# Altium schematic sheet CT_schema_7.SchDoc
size 430 x 429 mm
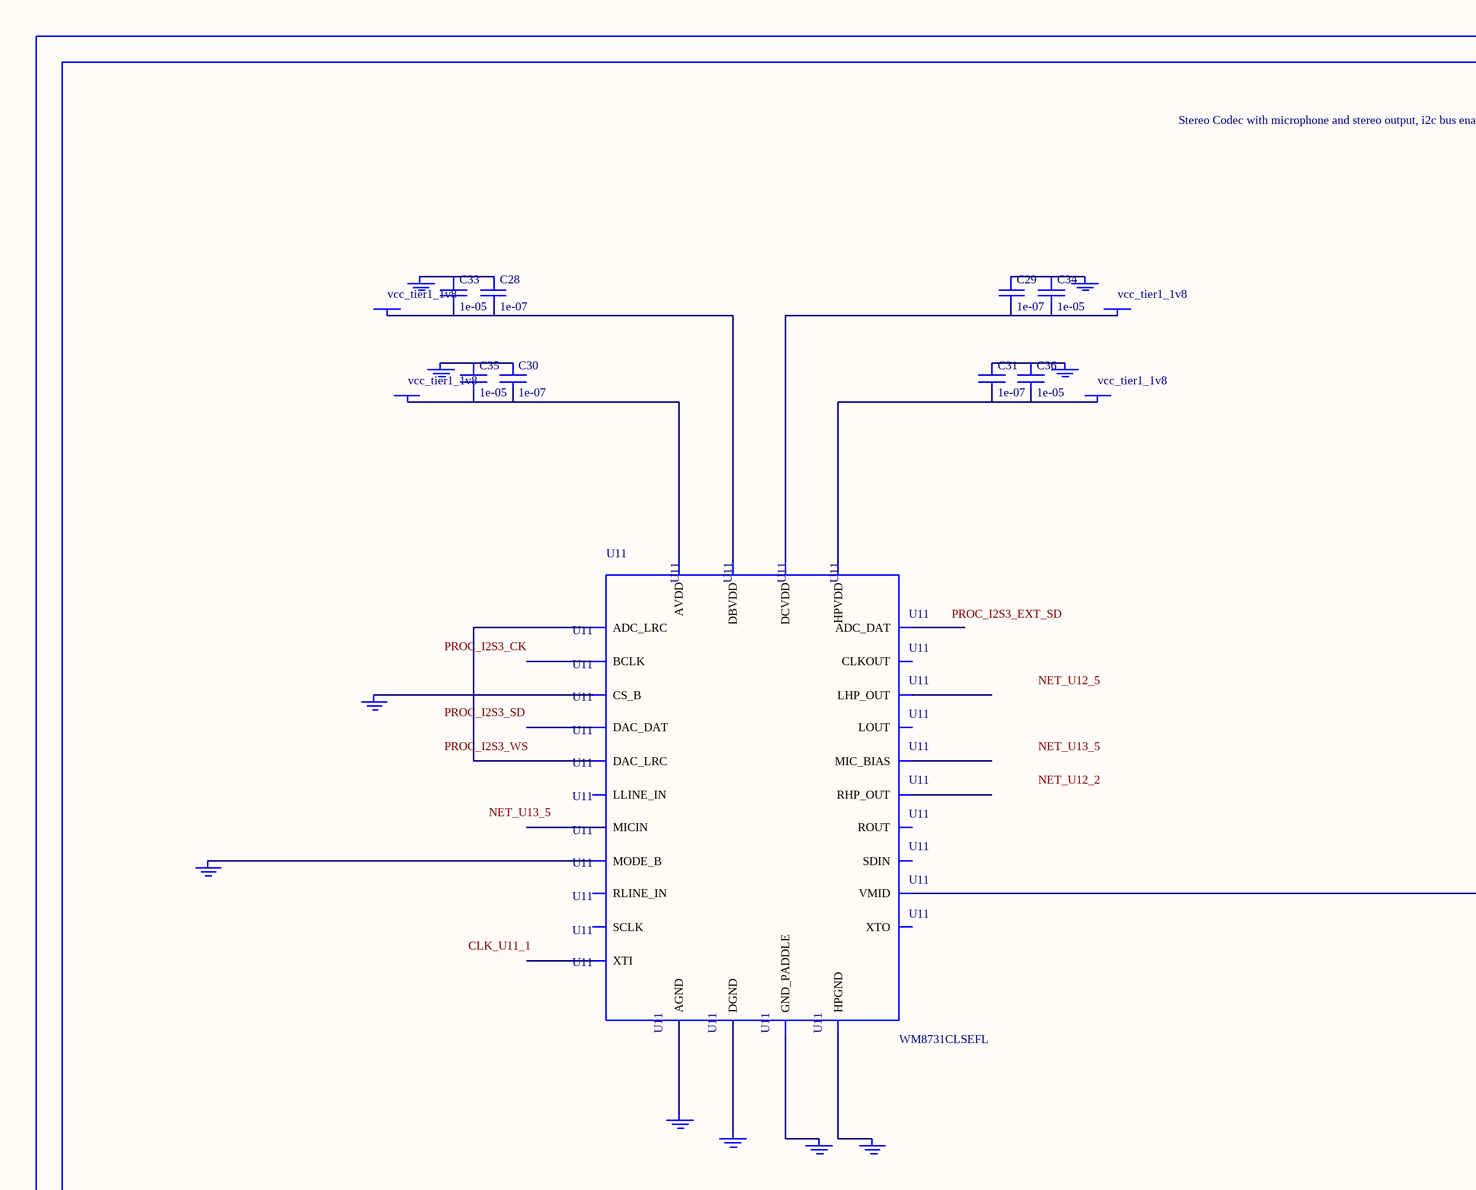
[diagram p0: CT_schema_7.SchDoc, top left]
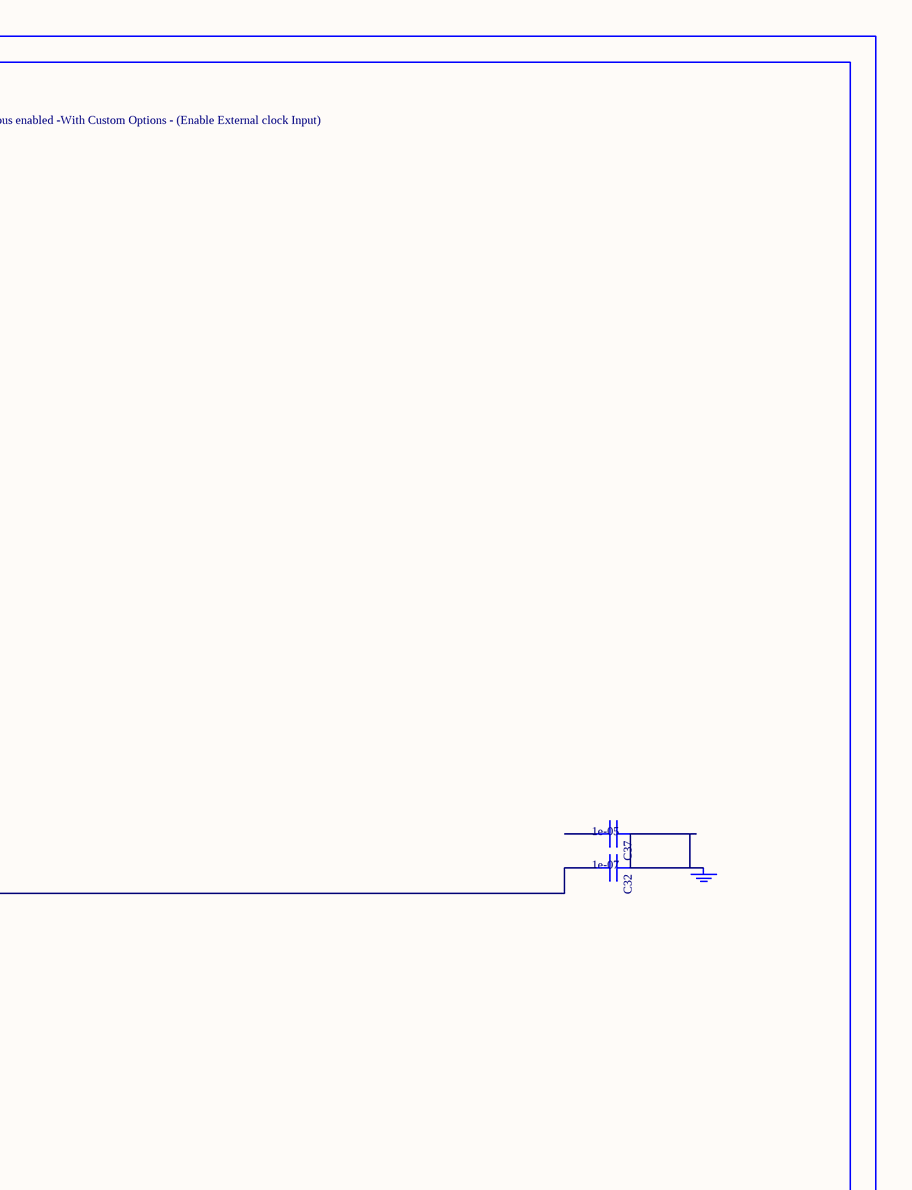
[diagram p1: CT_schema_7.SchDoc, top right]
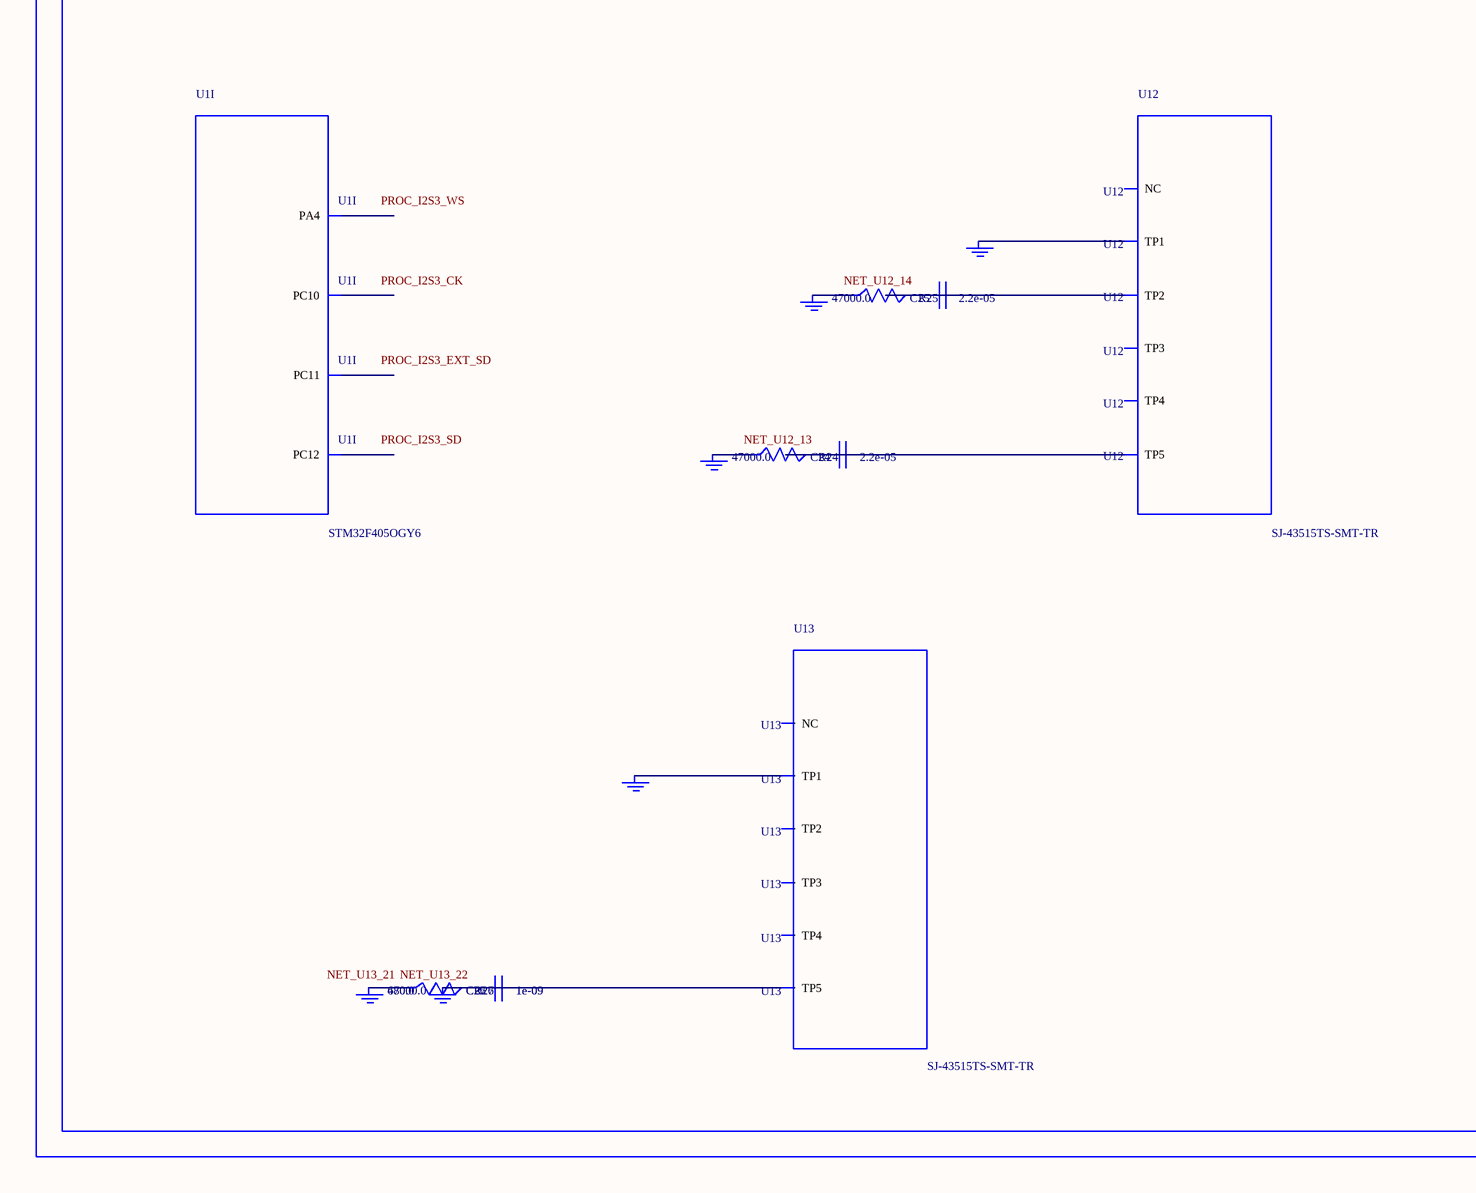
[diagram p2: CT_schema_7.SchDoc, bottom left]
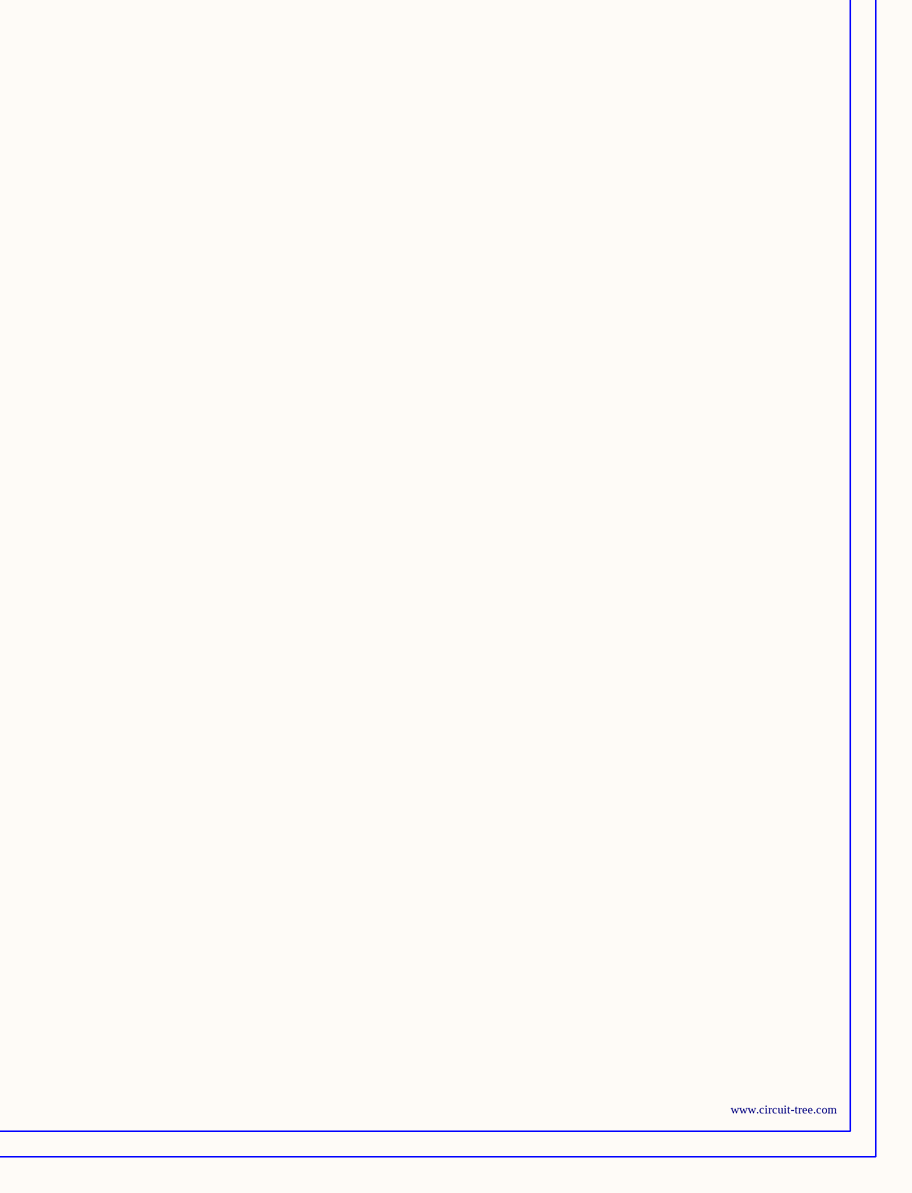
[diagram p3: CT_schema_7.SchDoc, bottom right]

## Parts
BORDER6  (no value)
C24  2.2e-05  [C1210]
C25  2.2e-05  [C1210]
C26  1e-09  [C0402]
C27  1e-09  [C0402]
C28  1e-07  [C0402]
C29  1e-07  [C0402]
C30  1e-07  [C0402]
C31  1e-07  [C0402]
C32  1e-07  [C0402]
C33  1e-05  [C0805]
C34  1e-05  [C0805]
C35  1e-05  [C0805]
C36  1e-05  [C0805]
C37  1e-05  [C0805]
GND_INSTANCE_6_0  (no value)
GND_INSTANCE_6_1  (no value)
GND_INSTANCE_6_2  (no value)
GND_INSTANCE_6_3  (no value)
GND_INSTANCE_6_4  (no value)
GND_INSTANCE_6_5  (no value)
GND_INSTANCE_6_6  (no value)
GND_INSTANCE_6_7  (no value)
GND_INSTANCE_6_8  (no value)
GND_INSTANCE_6_9  (no value)
GND_INSTANCE_6_10  (no value)
GND_INSTANCE_6_11  (no value)
GND_INSTANCE_6_12  (no value)
GND_INSTANCE_6_13  (no value)
GND_INSTANCE_6_14  (no value)
GND_INSTANCE_6_15  (no value)
GND_INSTANCE_6_16  (no value)
POWER_INSTANCE_6_0  vcc_tier1_1v8
POWER_INSTANCE_6_1  vcc_tier1_1v8
POWER_INSTANCE_6_2  vcc_tier1_1v8
POWER_INSTANCE_6_3  vcc_tier1_1v8
R24  47000.0  [R0603]
R25  47000.0  [R0603]
R26  47000.0  [R0603]
R27  680.0  [R0603]
U1  STM32F405OGY6  [WLCSP90]  (part I of 9)
U11  WM8731CLSEFL  [QFN-28]
U12  SJ-43515TS-SMT-TR  [SJ-43515TS-SMT-TR]
U13  SJ-43515TS-SMT-TR  [SJ-43515TS-SMT-TR]

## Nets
NetC24_1: C24.1 C24.2 R24.2 U12.5(TP5)
NetC25_1: C25.1 C25.2 R25.2 U12.2(TP2)
NetC26_1: C26.1 C26.2 C27.1 C27.2 GND_INSTANCE_6_16.0(GND) R26.2 R27.2 U13.5(TP5)
NetC28_1: C28.1 C33.1 GND_INSTANCE_6_1.0(GND)
NetC28_2: C28.2 C33.2 POWER_INSTANCE_6_1.0(PWR) U11.5(DBVDD)
NetC29_1: C29.1 C34.1 GND_INSTANCE_6_0.0(GND)
NetC29_2: C29.2 C34.2 POWER_INSTANCE_6_0.0(PWR) U11.3(DCVDD)
NetC30_1: C30.1 C35.1 GND_INSTANCE_6_4.0(GND)
NetC30_2: C30.2 C35.2 POWER_INSTANCE_6_3.0(PWR) U11.18(AVDD)
NetC31_1: C31.1 C36.1 GND_INSTANCE_6_2.0(GND)
NetC31_2: C31.2 C36.2 POWER_INSTANCE_6_2.0(PWR) U11.12(HPVDD)
NetC32_1: C32.1 C37.1 GND_INSTANCE_6_5.0(GND)
NetC32_2: C32.2 U11.20(VMID)
NetGND_INSTANCE_6_3_0: GND_INSTANCE_6_3.0(GND) U11.15(HPGND)
NetGND_INSTANCE_6_6_0: GND_INSTANCE_6_6.0(GND) U11.25(MODE_B)
NetGND_INSTANCE_6_7_0: GND_INSTANCE_6_7.0(GND) U11.26(CS_B)
NetGND_INSTANCE_6_8_0: GND_INSTANCE_6_8.0(GND) U11.29(GND_PADDLE)
NetGND_INSTANCE_6_9_0: GND_INSTANCE_6_9.0(GND) U11.4(DGND)
NetGND_INSTANCE_6_10_0: GND_INSTANCE_6_10.0(GND) U11.19(AGND)
NetGND_INSTANCE_6_11_0: GND_INSTANCE_6_11.0(GND) U12.1(TP1)
NetGND_INSTANCE_6_12_0: GND_INSTANCE_6_12.0(GND) R25.1
NetGND_INSTANCE_6_13_0: GND_INSTANCE_6_13.0(GND) R24.1
NetGND_INSTANCE_6_14_0: GND_INSTANCE_6_14.0(GND) U13.1(TP1)
NetGND_INSTANCE_6_15_0: GND_INSTANCE_6_15.0(GND) R26.1 R27.1
NetU11_9: U11.9(DAC_LRC) U11.11(ADC_LRC)

Not connected (* = marked no-connect by the designer): C37 2; U1 A3(PC12) C4(PC11) D5(PC10) J9(PA4); U11 1(XTI) 2(XTO) 6(CLKOUT) 7(BCLK) 8(DAC_DAT) 10(ADC_DAT) 13(LHP_OUT) 14(RHP_OUT) 16(LOUT) 17(ROUT) 21(MIC_BIAS) 22(MICIN) 23(RLINE_IN) 24(LLINE_IN) 27(SDIN) 28(SCLK); U12 3(TP3) 4(TP4) 6(NC); U13 2(TP2) 3(TP3) 4(TP4) 6(NC)

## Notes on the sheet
- Labels drawn without touching a wire or pin: CLK_U11_1, NET_U12_2, NET_U12_5, NET_U12_13, NET_U12_14, NET_U13_5, NET_U13_21, NET_U13_22, PROC_I2S3_CK, PROC_I2S3_EXT_SD, PROC_I2S3_SD, PROC_I2S3_WS

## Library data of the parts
BORDER6 = BORDER_PAGE6
C24 C25 = C1210C224K5RACTU
C26 C27 = C0402C102K3RAC
C28-C32 = C0402C104K3RACTU
C33-C37 = C0805C106K8RACTU
GND_INSTANCE_6_0-GND_INSTANCE_6_16 = GND
POWER_INSTANCE_6_0-POWER_INSTANCE_6_3 = PWR
R24-R26 = RC0603JR-0747KL
R27 = RC0603JR-07680RL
